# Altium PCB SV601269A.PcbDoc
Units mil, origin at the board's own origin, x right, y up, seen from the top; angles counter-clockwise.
Board outline 2000 x 3100 mil, 4 copper layers (Top Layer, GND_PLANE, POWER_PLANE, Bottom Layer), stack 60.8 mil thick; 63 components, 34 nets, 195 pads, 55 vias.
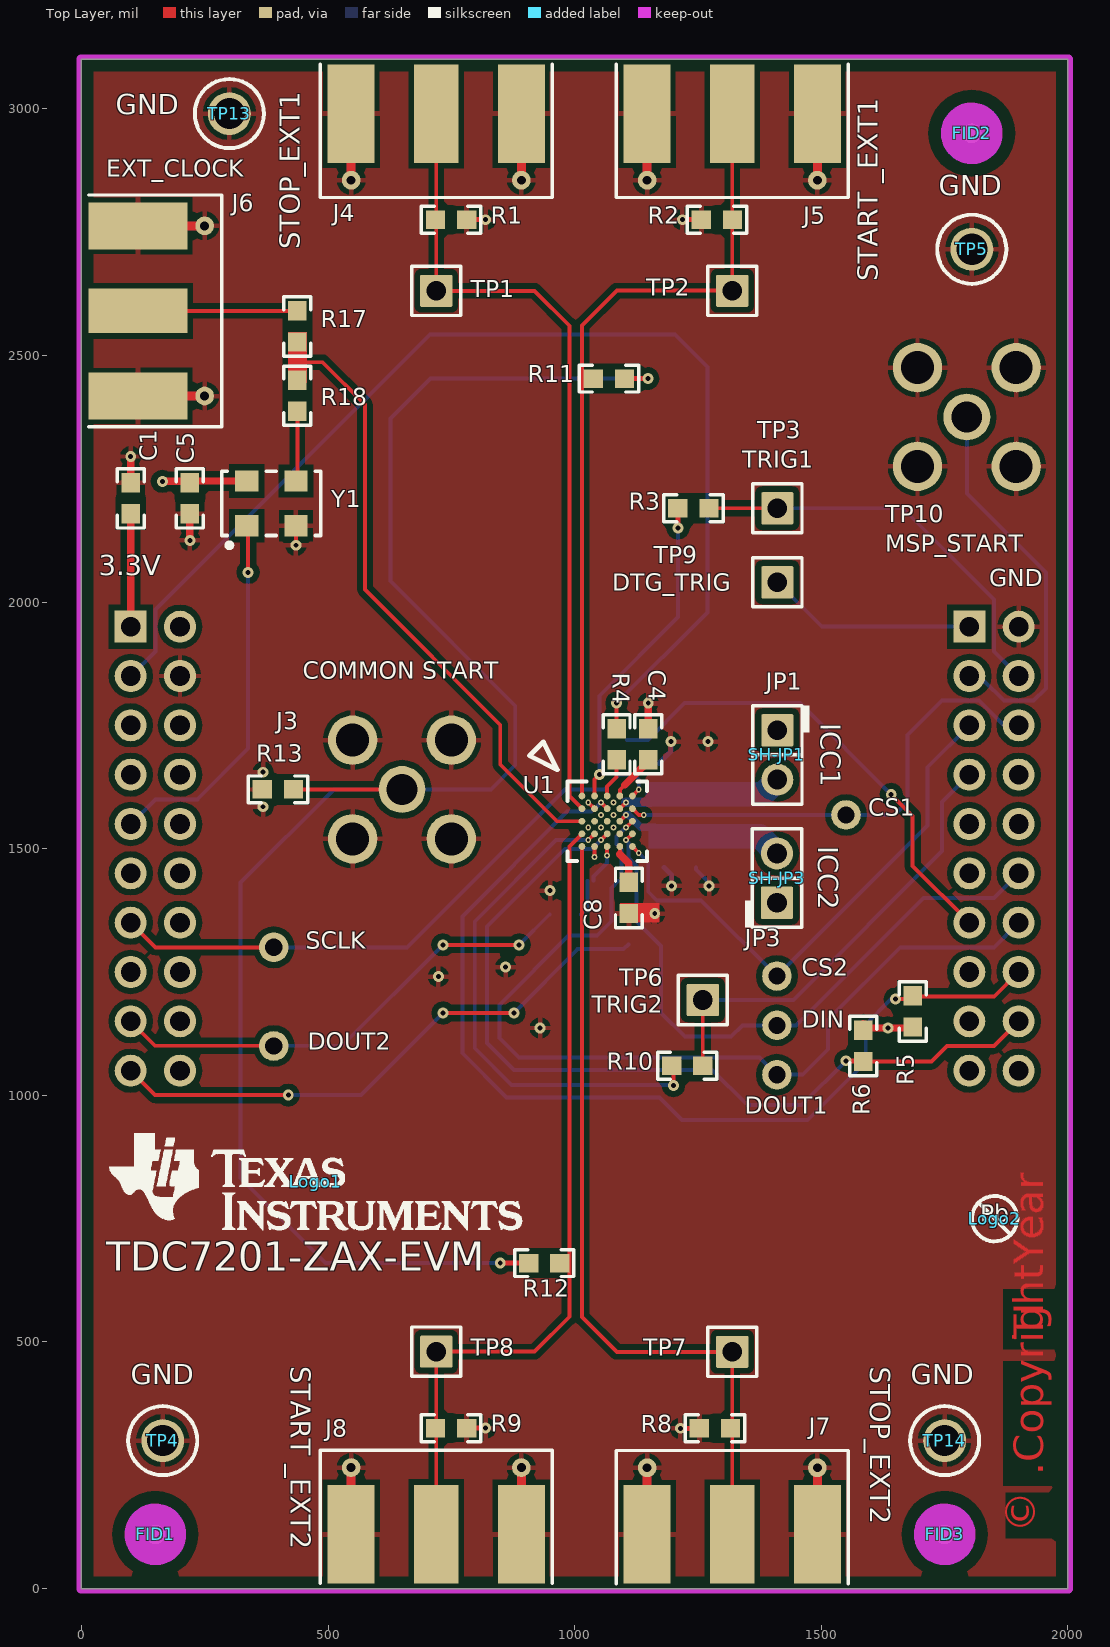
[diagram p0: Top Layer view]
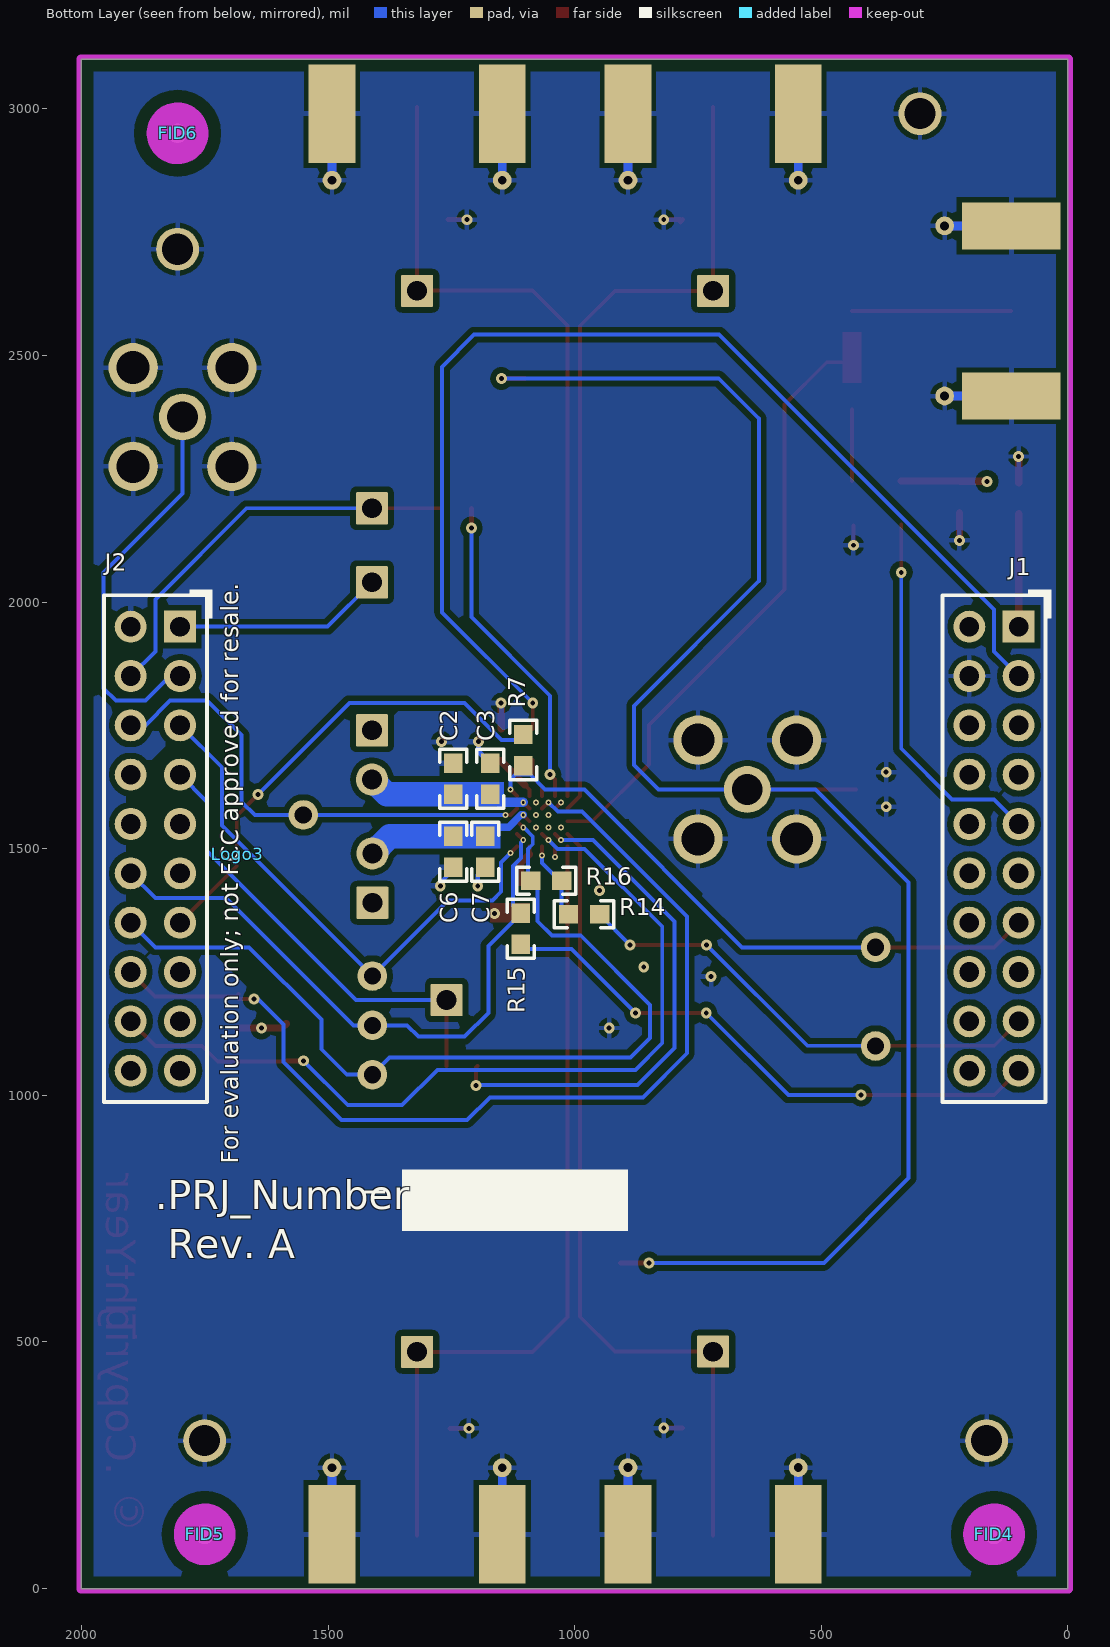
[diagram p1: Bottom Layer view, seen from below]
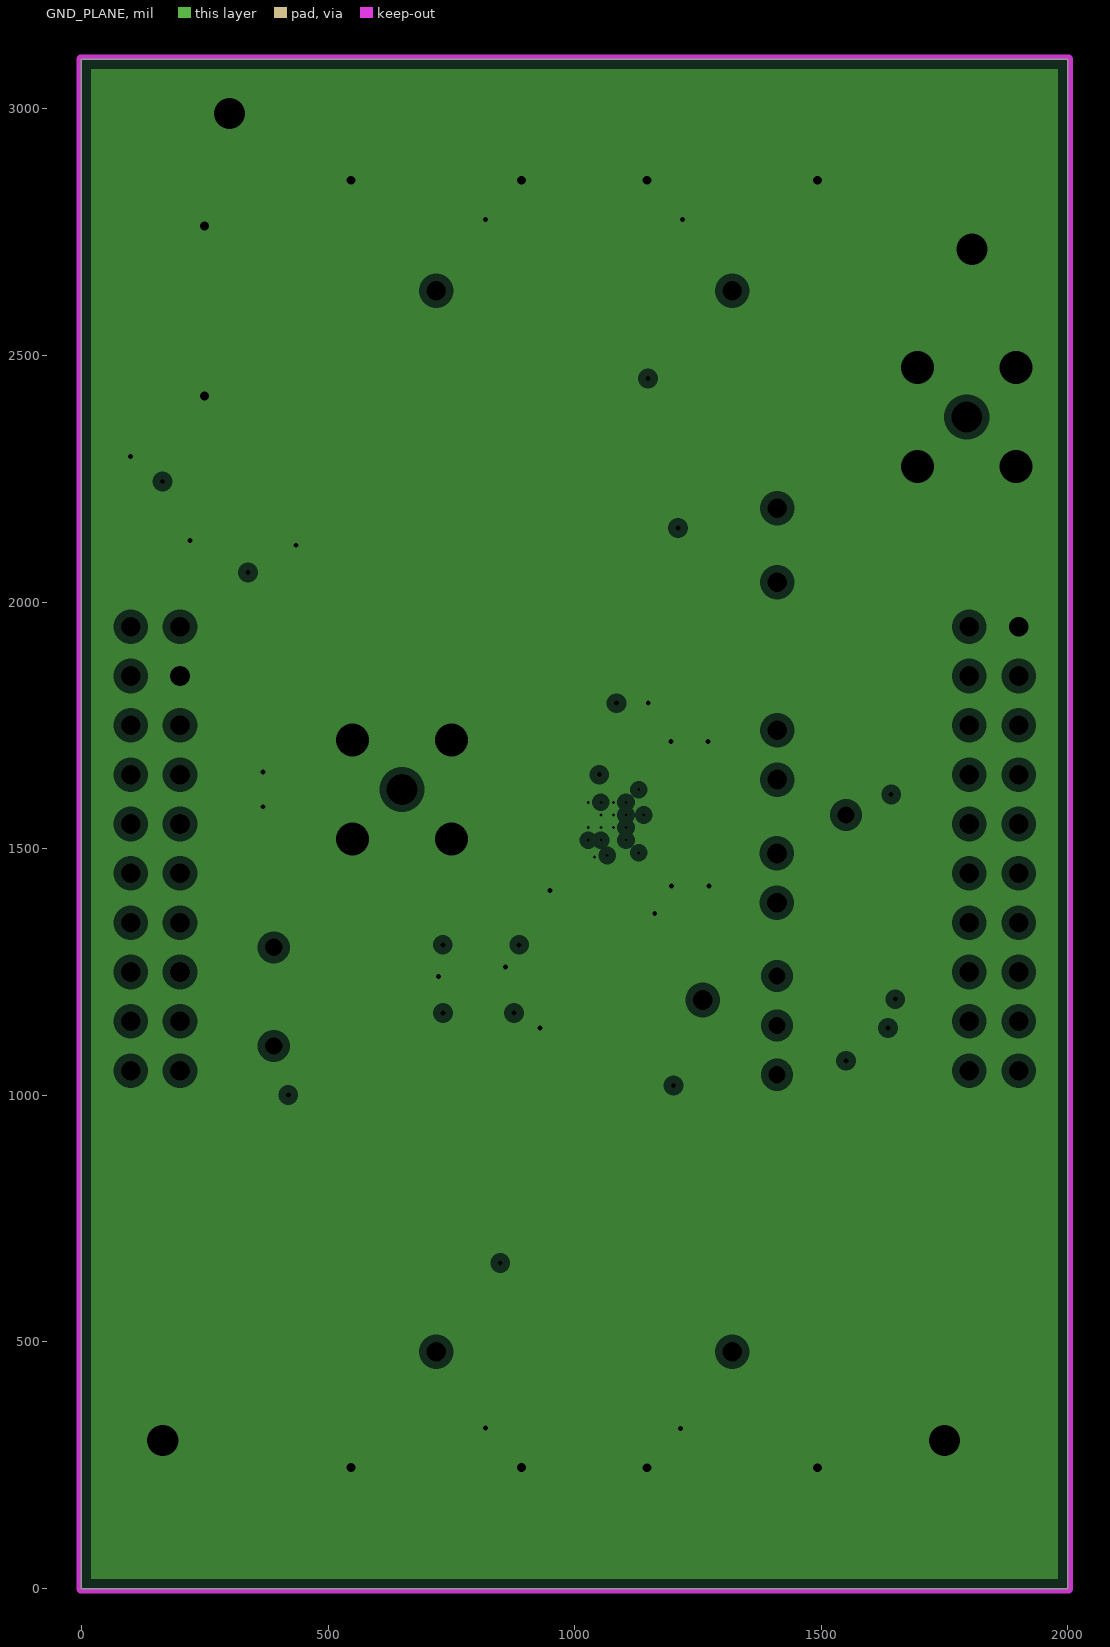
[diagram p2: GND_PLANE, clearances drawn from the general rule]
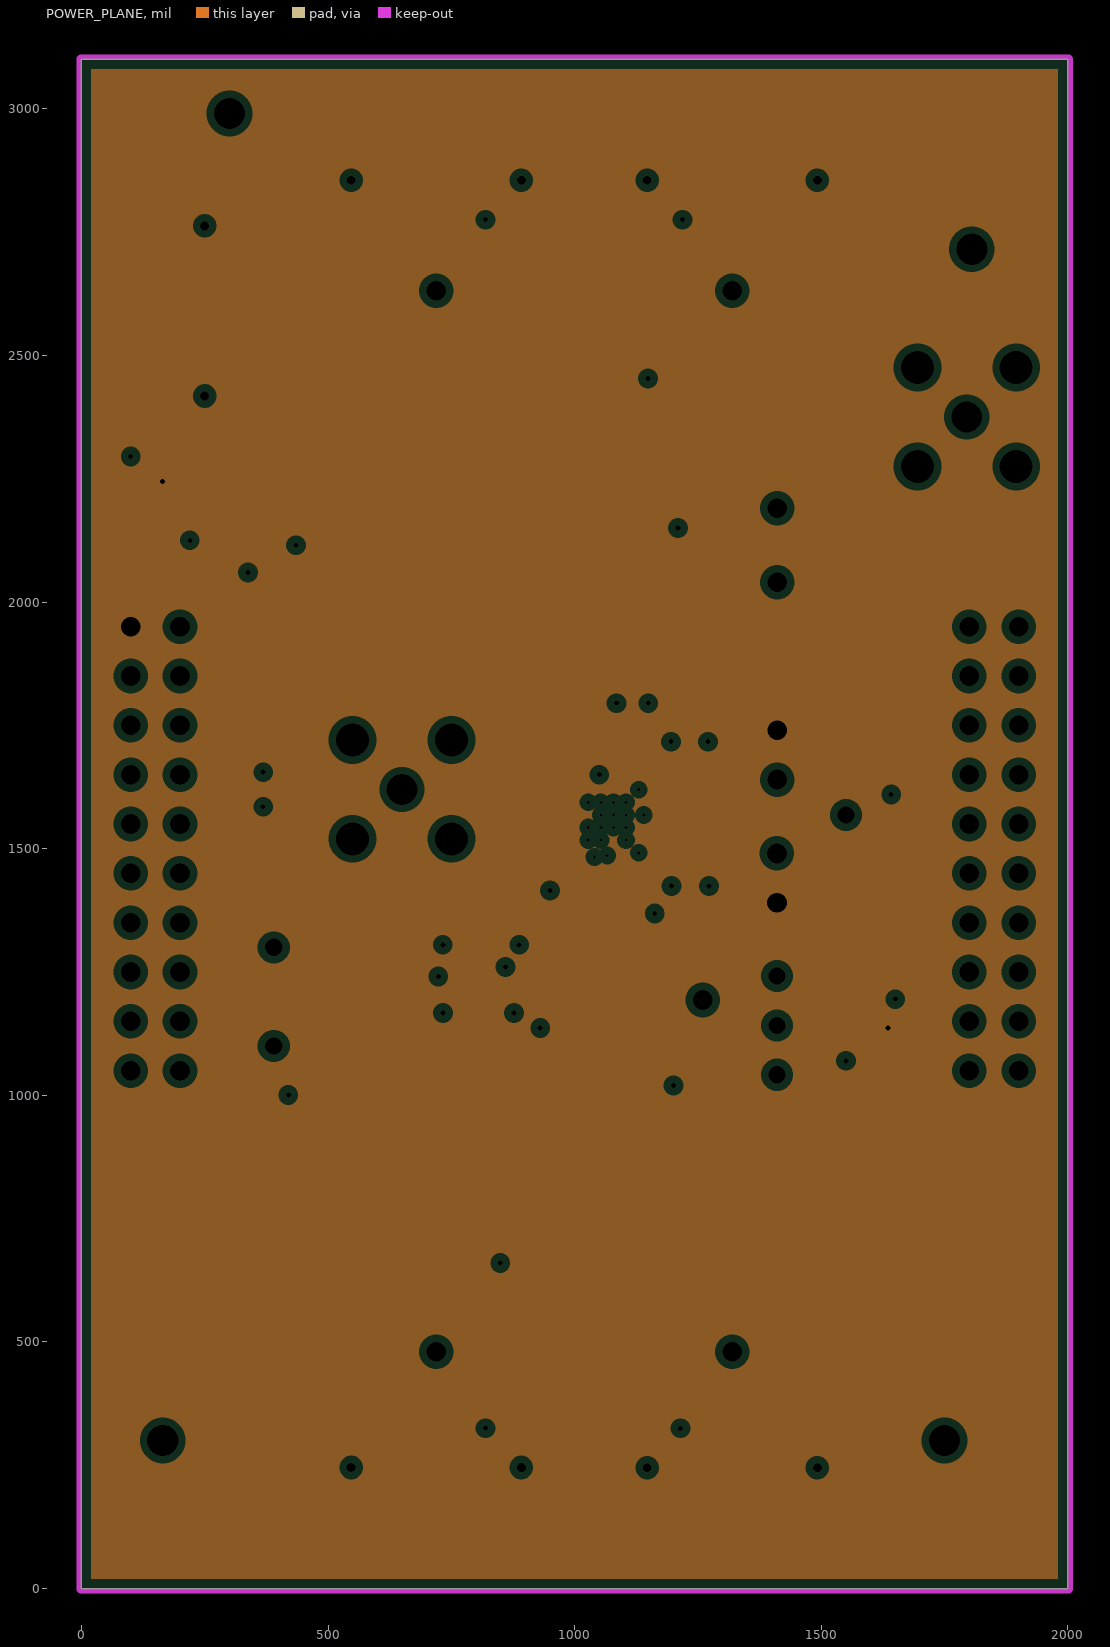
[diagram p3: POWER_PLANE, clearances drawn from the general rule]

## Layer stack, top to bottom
Top Solder: solder mask 0.4, Solder Resist, Dk 3.5
Top Layer: signal copper 1.4
Dielectric1: core 12.6, FR-4 High TG, Dk 4.8
GND_PLANE: plane copper 1.4, net GND
Dielectric2: prepreg 30, FR-4 High TG, Dk 4.8
POWER_PLANE: plane copper 1.4, net VCC
Dielectric3: core 12.6, FR-4 High TG, Dk 4.8
Bottom Layer: signal copper 1.4
Bottom Solder: solder mask 0.4, Solder Resist, Dk 3.5

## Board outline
0,0 0,3100 2000,3100 2000,0

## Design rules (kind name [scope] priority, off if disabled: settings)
AcuteAngle [All] p1: minimum=4.50000000000000E+0001 checktracksonly=FALSE
AssemblyTestPointUsage [All] p1: valid=2
Clearance Clearance_BoardEdge_MountingHoles [OnCopper and InComponentClass('Mounting Holes') vs IsKeepOut] p1: gap=40
Clearance Clearance_BoardEdge_Poly [OnCopper and InPoly vs IsKeepOut] p2: gap=25
Clearance Clearance_BoardEdge [OnCopper and Not InComponentClass('Logo') and not InComponentClass('FiducialMark') and not InRegion(1000,500,4000,800) and Not IsKeepout vs IsKeepOut] p3: gap=5
Clearance Clearance_Poly [InPolygon] p4: gap=12
Clearance [All] p5: gap=6 except(5: Track-THPad SMDPad-Via THPad-Via)
ComponentClearance ComponentClearance_shunt [InComponentClass('Header') vs InComponentClass('Shunt')] p1: gap=0 collisioncheckmode=3 verticalgap=0 showdistances=FALSE
ComponentClearance ComponentClearance_Logo [InComponentClass('Logo')] p2: gap=0 collisioncheckmode=3 verticalgap=0 showdistances=FALSE
ComponentClearance ComponentClearance_ScrewToNut [(HasFootprint('NY PMS 440 0025 PH')) vs (HasFootprint('Keystone_1902C'))] p3: gap=5 collisioncheckmode=3 verticalgap=10 showdistances=FALSE
ComponentClearance ComponentClearance_MountingHoles [InComponentClass('Mounting Holes')] p4: gap=250 collisioncheckmode=3 verticalgap=100000 showdistances=FALSE
ComponentClearance ComponentClearance_SmallPassives [HasFootprint('0201*') or HasFootprint('0402*') or HasFootprint('0508') or HasFootprint('0603*') or HasFootprint('0612') or HasFootprint('0805*') or HasFootprint('0815*') or HasFootprint('0830*') or HasFootprint('1206*') or HasFootprint('1210*') or HasFootprint('1808*') or HasFootprint('1812*') or HasFootprint('1825*') or HasFootprint('2010*') or HasFootprint('2220*') or HasFootprint('2225*') or HasFootprint('2512*') or HasFootprint('2728*') or HasFootprint('3518*') vs HasFootprint('0201*') or HasFootprint('0402*') or HasFootprint('0508') or HasFootprint('0603*') or HasFootprint('0612') or HasFootprint('0805*') or HasFootprint('0815*') or HasFootprint('0830*') or HasFootprint('1206*') or HasFootprint('1210*') or HasFootprint('1808*') or HasFootprint('1812*') or HasFootprint('1825*') or HasFootprint('2010*') or HasFootprint('2220*') or HasFootprint('2225*') or HasFootprint('2512*') or HasFootprint('2728*') or HasFootprint('3518*')] p5: gap=20 collisioncheckmode=3 verticalgap=10 showdistances=FALSE
ComponentClearance ComponentClearance_THtoSMT [IsThruComponent vs IsSMTComponent] p6: gap=20 collisioncheckmode=3 verticalgap=30 showdistances=FALSE
ComponentClearance ComponentClearance_THtoTH [IsThruComponent vs IsThruComponent] p7: gap=20 collisioncheckmode=3 verticalgap=30 showdistances=FALSE
ComponentClearance [All] p8: gap=40 collisioncheckmode=3 verticalgap=10 showdistances=FALSE
DiffPairsRouting [All] p1: maxlimit=100 minlimit=10 mostfreqgap=10 toplayer_minwidth=15 toplayer_maxwidth=15 toplayer_prefwidth=15 bottomlayer_minwidth=15 bottomlayer_maxwidth=15 bottomlayer_prefwidth=15 maxuncoupledlength=1000
FabricationTestPointUsage TestPointUsage [All] p1: valid=2 allowmultiple=FALSE
FabricationTestpoint Testpoint [All] p1: side=3 testpointundercomponent=TRUE minsize=40 maxsize=100 preferedsize=60 minholesize=0 maxholesize=40 preferedholesize=32 testpointgrid=1 allowsidetop=TRUE allowsidebottom=TRUE usegrid=TRUE gridtolerance=0.01
FanoutControl Fanout_LCC [IsLCC] p1: bgadir=Out bgaviamode=Centered fanoutstyle=Auto fanoutdirection=Alternating viagrid=1 // Fanout_LCC (Default Rule)
FanoutControl Fanout_BGA [IsBGA] p2: bgadir=Out bgaviamode=Centered fanoutstyle=Auto fanoutdirection=Alternating viagrid=1 // Fanout_BGA (Default Rule)
FanoutControl Fanout_Default [All] p4: bgadir=Out bgaviamode=Centered fanoutstyle=Auto fanoutdirection=Alternating viagrid=1 // Fanout_Default (Default Rule)
FanoutControl Fanout_Small [(CompPinCount < 5)] p5: bgadir=Out bgaviamode=Centered fanoutstyle=Auto fanoutdirection=OutThenIn viagrid=1 // Fanout_Small (Default Rule)
HoleSize [All] p1: absolutevalues=TRUE maxlimit=251 minlimit=6 maxpercent=80.000 minpercent=20.000
MinimumAnnularRing [All] p1: minimumring=3
MinimumSolderMaskSliver MinimumSolderMaskSliver_Logo [InComponentClass('Logo') vs InComponentClass('Logo')] p1: minsoldermaskwidth=0.7
MinimumSolderMaskSliver [All] p2: minsoldermaskwidth=4
PlaneClearance [All] p1: clearance=15
PlaneConnect PlaneConnect_Thermal_Vias [IsVia] p1: planeconnectstyle=Direct reliefexpansion=20 reliefentries=4 reliefconductorwidth=10 reliefairgap=10
PlaneConnect [All] p2: planeconnectstyle=Relief reliefexpansion=10 reliefentries=4 reliefconductorwidth=10 reliefairgap=10
PolygonConnect [All] p1: connectstyle=Relief reliefconductorwidth=10 reliefentries=4 polygonreliefangle="90 Angle" airgapwidth=10
RoutingVias [All] p1: holewidth=16 width=34 viastyle="Through Hole" minholewidth=6 minwidth=12 maxholewidth=40 maxwidth=65
SMDToCorner [All] p1: distance=16000
SilkToSilkClearance SilkToSilkClearance_Pb_FREE_LOGO [(HasFootprint('Pb-Free_Overlay_Medium') OR HasFootprint('Pb-Free_Overlay_Small')) vs (HasFootprint('Pb-Free_Overlay_Medium') OR HasFootprint('Pb-Free_Overlay_Small'))] p1: silktosilkclearance=0
SilkToSilkClearance [All] p2: silktosilkclearance=4
SilkToSolderMaskClearance SilkscreenOverComponentPads [IsPad] p1: minsilkscreentomaskgap=4 clearancetoexposedcopper=TRUE
SolderMaskExpansion [All] p1: expansion=1
Width [All] p1: maxlimit=100 minlimit=7.8 preferedwidth=10
15 further rules are at their usual default settings.

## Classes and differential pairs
component class AssemblyNote: ZZ1 ZZ2
component class Header: JP1 JP3 TP1 TP2 TP3 TP6 TP7 TP8 TP9
component class Shunt: SH-JP1 SH-JP3
component class Logo: Logo1
component class FiducialMark: FID1 FID2 FID3 FID4 FID5 FID6

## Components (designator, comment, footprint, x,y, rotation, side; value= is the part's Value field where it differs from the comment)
C1 "C0603C106M9PACTU" 0603 100,2210 r90 top
C2 "0603YC104JAT2A" 0603 1245.97,1641.5 r90 bottom
C3 "06031C103JAT2A" 0603 1170.97,1641.5 r90 bottom
C4 "EMK107B7105KA-T" 0603 1149.12,1711.5 r270 top
C5 "06031C103JAT2A" 0603 220,2210 r270 top
C6 "0603YC104JAT2A" 0603 1245.97,1493.5 r270 bottom
C7 "06031C103JAT2A" 0603 1180.97,1493.5 r270 bottom
C8 "EMK107B7105KA-T" 0603 1110,1400 r90 top
FID1 "Fiducial" Fiducial10-30 150,110 r0 top
FID2 "Fiducial" Fiducial10-30 1805,2950 r0 top
FID3 "Fiducial" Fiducial10-30 1750,110 r0 top
FID4 "Fiducial" Fiducial10-30 150,110 r180 bottom
FID5 "Fiducial" Fiducial10-30 1750,110 r180 bottom
FID6 "Fiducial" Fiducial10-30 1805,2950 r180 bottom
J1 "PPPC102LFBN-RC" Sullins_PPPC102LFBN-RC 150,1500 r90 bottom
J2 "PPPC102LFBN-RC" Sullins_PPPC102LFBN-RC 1850,1500 r90 bottom
J3 "142-0701-201" Johnson_142-0701-20x 650,1620 r180 top
J4 "142-0701-801" JOHNSON_142-0701-801 719.41,2990 r0 top
J5 "142-0701-801" JOHNSON_142-0701-801 1319.41,2990 r0 top
J6 "142-0701-801" JOHNSON_142-0701-801 115,2590 r90 top
J7 "142-0701-801" JOHNSON_142-0701-801 1319.41,110.03 r180 top
J8 "142-0701-801" JOHNSON_142-0701-801 719.41,110.41 r180 top
JP1 "TSW-102-07-G-S" TSW-102-07-G-S 1410.83,1690 r270 top
JP3 "TSW-102-07-G-S" TSW-102-07-G-S 1410,1440.35 r90 top
Logo1 "Texas Instruments" TI_Stacked_Overlay_Small 475,825 r0 top
Logo2 "Pb-Free Symbol" Pb-Free_Overlay_Small 1851.28,750 r0 top
Logo3 "FCC disclaimer" FCC_disclaimer 1683.24,1488.87 r90 bottom
R1 "CRCW060349R9FKEA" 0603 749.41,2775 r180 top
R2 "CRCW060349R9FKEA" 0603 1288.41,2775 r0 top
R3 "CRCW06030000Z0EA" 0603 1240.83,2190 r0 top
R4 "CRCW06030000Z0EA" 0603 1085,1711.5 r90 top
R5 "CRCW060310K0FKEA" 0603 1685,1170 r270 top
R6 "CRCW060310K0FKEA" 0603 1585,1100 r90 top
R7 "CRCW06030000Z0EA" 0603 1104.27,1700 r90 bottom
R8 "CRCW060349R9FKEA" 0603 1284.41,325.03 r0 top
R9 "CRCW060349R9FKEA" 0603 749.41,325.41 r180 top
R10 "CRCW06030000Z0EA" 0603 1228.15,1059.72 r0 top
R11 "CRCW06030000Z0EA" 0603 1069.5,2453 r180 top
R12 "CRCW06030000Z0EA" 0603 938.5,660 r0 top
R13 "CRCW060349R9FKEA" 0603 398.5,1620 r0 top
R14 "CRCW06030000Z0EA" 0603 981,1367 r0 bottom
R15 "CRCW06030000Z0EA" 0603 1109,1337.45 r90 bottom
R16 "CRCW06030000Z0EA" 0603 1057.8,1435 r180 bottom
R17 "CRCW06030000Z0EA" 0603 438,2558.5 r90 top
R18 "CRCW06030000Z0EA" 0603 438,2418 r90 top
SH-JP1 "969102-0000-DA" SNT-100-BK-G 1410,1690 r90 top
SH-JP3 "969102-0000-DA" SNT-100-BK-G 1411,1439.64 r90 top
TP1 "TSW-101-07-G-S" TSW-101-07-G-S 719.41,2630.77 r0 top
TP2 "TSW-101-07-G-S" TSW-101-07-G-S 1319.41,2630.77 r0 top
TP3 "TSW-101-07-G-S" TSW-101-07-G-S 1410.83,2190 r0 top
TP4 "5011" Keystone5011 165,300 r0 top
TP5 "5011" Keystone5011 1805,2715 r0 top
TP6 "TSW-101-07-G-S" TSW-101-07-G-S 1259.65,1193.22 r180 top
TP7 "TSW-101-07-G-S" TSW-101-07-G-S 1319.41,480.03 r180 top
TP8 "TSW-101-07-G-S" TSW-101-07-G-S 719.41,480.41 r180 top
TP9 "TSW-101-07-G-S" TSW-101-07-G-S 1410.83,2040 r0 top
TP10 "142-0701-201" Johnson_142-0701-20x 1795,2375 r90 top
TP13 "5011" Keystone5011 300,2990 r0 top
TP14 "5011" Keystone5011 1750,300 r0 top
U1 "TDC7201ZAXR" ZAX0025A 1065.88,1555.59 r0 top locked
Y1 "ASFLMB-8.000MHZ-LY-T" Abracon_ASFLMB 385,2200 r90 top
ZZ1 "Short SH-JP1 on JP1 pin 1-2" AssemblyNote 175,3820 r0 top
ZZ2 "Short SH-JP3 on JP3 pin 1-2" AssemblyNote 175,3700 r0 top

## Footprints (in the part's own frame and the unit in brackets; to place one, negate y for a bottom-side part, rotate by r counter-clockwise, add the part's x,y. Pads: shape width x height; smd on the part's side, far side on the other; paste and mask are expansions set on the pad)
0603 [mm] "0603 from SM-752 data"
  rect 1x0.95 smd: 1(-0.8,0) 2(0.8,0)
  silkscreen extent -1.52,-0.69 1.52,0.69, body extent -0.87,-0.47 0.87,0.47, height 1
Abracon_ASFLMB [mm] "Abracon"
  rect 1.1x1.2 smd: 1(-1.15,1.27) 2(-1.15,-1.27) 3(1.15,-1.27) 4(1.15,1.27)
  silkscreen extent -2.29,-2.55 1.65,2.55, body extent -1.65,-2.55 1.65,2.55, height 0.9
AssemblyNote [mil] "Assembly Note"
FCC_disclaimer [mil]
Fiducial10-30 [mm]
  round 1 smd mask+1: 1(0,0)
  Top Layer keep-out circle w1.678: c0,0 r0.75
Johnson_142-0701-20x [mil] "Johnson Components recommended land pattern"
  round 95 hole 62: 1(0,0)
  round 100 hole 67: 2(100,100) 3(100,-100) 4(-100,-100) 5(-100,100)
  body extent -156,-156 156,156, height 375
JOHNSON_142-0701-801 [mil] "Johnson Components recommended land pattern"
  rect 90x200 smd: 1(0,0)
  round 38 hole 18: 2(-172.5,-135) 3(172.5,-135)
  rect 95x200 smd: 2(-172.5,0) 3(172.5,0)
  rect 95x200 smd far side: 4(-172.5,0) 5(172.5,0)
  Top Layer lines w18: -172.5,-135 -172.5,0 ; 172.5,-135 172.5,0
  Bottom Layer lines w18: -172.5,-135 -172.5,0 ; 172.5,-135 172.5,0
  silkscreen extent -235,-170 235,100, body extent -190,-92 190,480, height 165
Keystone5011 [mil] "Keystone Multipurpose loops"
  round 87 hole 63: 1(0,0)
  silkscreen extent -70,-70 70,70, body extent -63,-63 63,62, height 319
Pb-Free_Overlay_Small [mil]
  silkscreen extent -46,-46 46,46
SNT-100-BK-G [mil] "Samtec STEP model"
  round 1 on Mech3: 0(0,0)
  body extent -100,-50 100,50, height 344
Sullins_PPPC102LFBN-RC [mil] "Sullins"
  rect 65x65 hole 40: 1(450,-50)
  round 65 hole 40: 2(450,50) 3(350,-50) 4(350,50) 5(250,-50) 6(250,50) 7(150,-50) 8(150,50) 9(50,-50) 10(50,50) 11(-50,-50) 12(-50,50) 13(-150,-50) 14(-150,50) 15(-250,-50) 16(-250,50) 17(-350,-50) 18(-350,50) 19(-450,-50) 20(-450,50)
  silkscreen extent -514,-116 526,104, body extent -514,-104 514,104, height 335
TI_Stacked_Overlay_Small [mil]
  silkscreen extent -418,-98 418,98
TSW-101-07-G-S [mm] "Samtec 100mil, 1pos, 230 mil above insulator"
  rrect6% 1.65x1.65 hole 1.016: 1(0,0)
  silkscreen extent -1.27,-1.27 1.27,1.27, body extent -1.27,-1.27 1.27,1.27, height 8.38
TSW-102-07-G-S [mm] "Samtec 100mil, 1x2, 230 mil above insulator"
  rrect6% 1.65x1.65 hole 1.016: 1(-1.27,0)
  round 1.65 hole 1.016: 2(1.27,0)
  silkscreen extent -2.54,-1.27 2.54,1.65, body extent -2.54,-1.27 2.54,1.27, height 8.38
ZAX0025A [mm] "BGA, 25-Leads, Body 4x4mm, Pitch 0.65mm"
  round 0.35 smd mask+0: A1(-1.3,1.3) A2(-0.65,1.3) A3(0,1.3) A4(0.65,1.3) A5(1.3,1.3) B1(-1.3,0.65) B2(-0.65,0.65) B3(0,0.65) B4(0.65,0.65) B5(1.3,0.65) C1(-1.3,0) C2(-0.65,0) C3(0,0) C4(0.65,0) C5(1.3,0) D1(-1.3,-0.65) D2(-0.65,-0.65) D3(0,-0.65) D4(0.65,-0.65) D5(1.3,-0.65) E1(-1.3,-1.3) E2(-0.65,-1.3) E3(0,-1.3) E4(0.65,-1.3) E5(1.3,-1.3)
  silkscreen extent -2.05,-2.05 2.05,2.05, body extent -2.05,-2.05 2.05,2.05, height 1.2

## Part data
C1: "CAP, CERM, 10 µF, 6.3 V, +/- 20%, X5R, 0603"
C2 C6: "CAP, CERM, 0.1 µF, 16 V, +/- 5%, X7R, 0603"
C3 C5 C7: "CAP, CERM, 0.01 µF, 100 V, +/- 5%, X7R, 0603"
C4 C8: "CAP, CERM, 1 µF, 16 V, +/- 10%, X7R, 0603"
FID1 FID2 FID3 FID4 FID5 FID6: "Fiducial mark.  There is nothing to buy or mount."
J1 J2: "Receptacle, 100mil, 10x2, Gold, TH"
J3 TP10: "Connector, TH, SMA"
J4 J5 J6 J7 J8: "Connector, End launch SMA, 50 ohm, SMT"
JP1 JP3: "Header, 100mil, 2x1, Gold, TH"
Logo1: library part TI_Logo, "Texas Instrument Corporate Signature"
Logo2: library part Pb-Free
Logo3: library part FCC_disclaimer, "FCC_disclaimer"
R1 R2 R8 R9 R13: "RES, 49.9, 1%, 0.1 W, 0603"
R3 R4 R7 R10 R11 R12 R14 R15 R16 R17 R18: "RES, 0, 5%, 0.1 W, 0603"
R5 R6: "RES, 10.0 k, 1%, 0.1 W, 0603"
SH-JP1 SH-JP3: "Shunt, 100mil, Gold plated, Black"
TP1 TP2 TP3 TP6 TP7 TP8 TP9: "Header, 100mil, 1pos, Gold, TH"
TP4 TP5 TP13 TP14: "Test Point, Multipurpose, Black, TH"
U1: "Time-to-Digital Converter for Time-of-FlightApplications in LIDAR, Magnetostrictive andFlowMeters, ZAX0025A"
Y1: "OSC, 8MHz, 15pF, SMD"
ZZ1 ZZ2: library part AssemblyNote

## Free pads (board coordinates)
  round 60 hole 35: 0(390,1100) 0(390,1300) 0(1410,1041.77) 0(1410,1141.77) 0(1410,1241.77) 0(1550,1568.39)

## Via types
v1: diameter 22, hole 10, Top Layer to Bottom Layer, tented both sides, 36 vias
v2: diameter 12, hole 6, Top Layer to Bottom Layer, tented both sides, 19 vias

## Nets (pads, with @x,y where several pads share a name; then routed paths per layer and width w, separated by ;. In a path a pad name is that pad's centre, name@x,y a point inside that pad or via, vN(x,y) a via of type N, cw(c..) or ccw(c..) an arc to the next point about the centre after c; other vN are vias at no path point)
CLOCK_TDC_CAL: R17.1 R18.2 U1.C1 | length 1222.6
  Top Layer w8: 444,2486 489,2486 575,2400 575,2025 849.09,1750.91 849.09,1670.91 964.41,1555.59 U1.C1
CS1: J2.6 pad.0@1550,1568.39 U1.B5 | length 979
  Top Layer w8: U1.B5 1129.86,1568.39 v2(1140,1568.39)
  Bottom Layer w8: v2@1145,1568.39 1648.39,1568.39 1675,1595 1675,1730 1745,1800 1820,1800 1870,1750 J2.6
CS2: J2.5 pad.0@1410,1241.77 U1.E5 | length 1106.5
  Top Layer w8: U1.E5 v2(1129.86,1491.61)
  Bottom Layer w8: v2(1129.86,1491.61) 1149.12,1472.35 1149.12,1412.66 1166.44,1395.34 1256.44,1395.34 1410,1241.77 1715,1546.77 1715,1665 J2.5
DIN: J2.12 pad.0@1410,1141.77 R15.2 U1.D5 | length 1292.8
  Top Layer w8: v2(1104.27,1517.2) U1.D5
  Bottom Layer w8: v2(1104.27,1517.2) 1109,1512.47 1109,1481 1125,1465 1125,1384.94 R15.2 1175,1302.94 1175,1167.21 1223.31,1118.9 1317,1118.9 1339.87,1141.77 1410,1141.77 1448.57,1141.77 1706.8,1400 1850,1400 J2.12
DOUT1: J2.14 pad.0@1410,1041.77 R16.1 U1.C5 | length 1827.9
  Top Layer w8: v2(1104.27,1542.8) U1.C5
  Bottom Layer w8: R16.1 1075,1420.7 1075,1352.91 1045.8,1323.72 987.72,1323.72 847.5,1183.5 847.5,1116.42 887.23,1076.69 1375.08,1076.69 1410,1041.77 1461.77,1041.77 1513.39,1093.39 1513.39,1153.39 1660,1300 1850,1300 J2.14 ; R16.1@1095,1445 1095,1499 1085,1509 1085,1525 1102.8,1542.8 v2(1104.27,1542.8)
DOUT2: R14.2 R16.2 U1.E3 | length 154.5
  Top Layer w8: v2(1065.88,1486.31) U1.E3
  Bottom Layer w8: R14.2 1026.3,1380.81 R16.2 ; R16.2@1038.5,1435 1038.5,1443.5 1065.88,1470.88 v2(1065.88,1486.31)
DTG_TRIG: J2.1 TP9.1 | length 426.4
  Bottom Layer w8: TP9.1 1500.83,1950 J2.1
ENABLE1: J1.3 R4.2 | length 2342.4
  Top Layer w8: R4.2 v1(1085,1795)
  Bottom Layer w8: J1.3 150,1900 150,1985 707,2542 1203.65,2542 1269,2476.65 1269,1979 v1(1085,1795)
EXT_CLOCK: J6.1 R17.2 | length 323
  Top Layer w8: J6.1 R17.2
GND: C1.2 C2.2 C3.2 C4.1 C5.2 C6.2 C7.2 C8.1 J1.4 J2.2 J3.2 J3.3 J3.4 J3.5 J4.2 J4.3 J4.4 J4.5 J5.2 J5.3 J5.4 J5.5 J6.2 J6.3 J6.4 J6.5 J7.2 J7.3 J7.4 J7.5 J8.2 J8.3 J8.4 J8.5 R1.1 R2.1 R8.1 R9.1 R13.1 TP4.1 TP5.1 TP10.2 TP10.3 TP10.4 TP10.5 TP13.1 TP14.1 U1.B2 U1.E2 Y1.2 | length 545.9
  Top Layer w8: v1(435,2115) Y1.2 ; v2(1027.5,1593.98) U1.B2 ; v2(1040.29,1483.31) U1.E2
  Top Layer w10: R9.1 v1(819.41,325.41) ; R1.1 R1.1@785.91,2770 ; R1.1@785.91,2775 v1(819.41,2775) ; v1(1214.41,325.03) R8.1 ; v1(1218.41,2775) R2.1
  Top Layer w15: C1.2 v1(100,2295) ; v1(220,2125) C5.2@220,2181.5 ; C4.1 v1(1149.12,1795)
  Bottom Layer w8: v2(1027.5,1593.98) v2@1027.5,1594.95 ; v2(1040.29,1483.31) v2@1041.82,1483.31 ; C6.2 1245.97,1457.61 1272.36,1431.22 v1(1272.36,1424.5)
  Bottom Layer w10: C3.2 1195.07,1697.09 v1(1195.07,1717) ; C7.2 1196.5,1446.48 v1(1196.5,1424.5)
  other v1: 930,1136.5 723.7,1240.71 860,1260 1162.29,1368.5 950,1415 368.5,1585 368.5,1655 1270.07,1717
  other v2: 1027.5,1542.8 1053.09,1542.8 1078.68,1542.8 1053.09,1568.39 1078.68,1568.39 1078.68,1593.98
INT1: J2.16 R5.1 U1.B3 | length 2023.2
  Top Layer w8: v2(1053.09,1593.98) U1.B3 ; v1(1650,1195) R5.1@1681.5,1195 ; R5.1@1681.5,1205 R5.1 ; R5.1@1686,1200.5 1850.5,1200.5 J2.16
  Bottom Layer w8: v2@1053.09,1594.95 v2(1053.09,1593.98) 1034.11,1575 984.84,1575 772.5,1362.66 772.5,1085.35 861.85,996 1171.95,996 1217.95,950 1472.43,950 1590,1067.57 1590,1143.39 1641.61,1195 v1(1650,1195)
INT2: J2.18 R6.1 U1.D3 | length 1758.5
  Top Layer w8: v2(1053.09,1517.2) U1.D3 ; R6.1 1723.5,1068.5 1755,1100 1850,1100 J2.18
  Top Layer w10: v1(1550,1070) 1583.5,1070 R6.1
  Bottom Layer w8: v2(1053.09,1517.2) 1035.2,1499.31 979.87,1499.31 822.5,1341.95 822.5,1106.06 876.87,1051.69 1278.31,1051.69 1350,980 1460,980 v1(1550,1070)
MSP_START: J2.3 TP10.1 | length 802.3
  Bottom Layer w8: TP10.1 1795,2220 1955,2060 1955,1825 1930,1800 1870,1800 1830,1840 1825,1840 1815,1850 J2.3
NetJ1_17: J1.17 pad.0@390,1100 R14.1 | length 968.7
  Top Layer w8: J1.17 149.5,1100.5 pad.0@385,1100.5 ; v1@733.3,1305 876.3,1305
  Bottom Layer w8: pad.0@385,1100.5 528.3,1100.5 v1(732.8,1305) ; v1(887.5,1305) R14.1
NetJ1_19: J1.19 R15.1 | length 1156
  Top Layer w8: J1.19 149.5,1000.5 v1(419.5,1000.5) ; v1(733.3,1166.8) v1(876.8,1166.8)
  Bottom Layer w8: v1(419.5,1000.5) 566.99,1000.5 v1(733.3,1166.8) ; v1(876.8,1166.8) 1006.18,1296.18 1099.23,1296.18 R15.1
NetJ2_13: J2.13 R7.2 | length 968.7
  Top Layer w8: v1(1641.61,1610) 1685,1566.61 1685,1465 J2.13
  Bottom Layer w8: R7.2@1106,1720.5 1148.5,1720.5 1223,1795 1456.61,1795 v1(1641.61,1610)
NetJ3_1: J3.1 R11.1 R12.1 R13.2 | length 3539.8
  Top Layer w8: R13.2 J3.1
  Top Layer w10: v1(849.09,660) R12.1 ; R11.1 v1(1148.67,2453)
  Bottom Layer w8: v1(849.09,660) 495,660 323,832 323,1431 512,1620 J3.1 830,1620 879.6,1669.6 879.6,1789.4 626.8,2042.2 626.8,2371.8 708,2453 v1(1148.67,2453)
NetR3_1: R3.1 U1.A2 | length 653.2
  Top Layer w8: U1.A2 1040.29,1640.29 v1(1050,1650)
  Top Layer w10: v1(1209.33,2150) R3.1
  Bottom Layer w8: v1(1050,1650) 1050,1810 1209.33,1969.33 v1(1209.33,2150)
NetR4_1: R4.1 U1.A3 | length 81.1
  Top Layer w8: U1.A3 1065.88,1625.88 1085,1645 R4.1
NetR10_1: R10.1 U1.D2 | length 1048.6
  Top Layer w8: v2(1027.5,1517.2) U1.D2 ; R10.1 1200.16,1056.21 v1(1200.16,1019.72)
  Bottom Layer w8: v2(1027.5,1517.2) 962.4,1517.2 797.5,1352.3 797.5,1095.71 872.21,1021 1198.87,1021 v1(1200.16,1019.72)
OSC_ENABLE: J1.9 Y1.1 | length 755.1
  Top Layer w8: v1(338,2060) Y1.1@338,2156.69
  Bottom Layer w8: J1.9 150,1600 235,1600 338,1703 v1(338,2060)
OSC_OUT: R18.1 Y1.3 | length 144.7
  Top Layer w8: Y1.3@438,2245.28 R18.1@438,2390
SCLK: J1.13 pad.0@390,1300 R7.1 U1.A5 | length 1238.2
  Top Layer w8: J1.13 150,1300 pad.0@390,1300 ; U1.A5 v2(1129.86,1619.57)
  Bottom Layer w8: pad.0@390,1300 660.4,1300 980.4,1620 1060,1620 1090,1650 1119.86,1650 1129.86,1640 v2(1129.86,1619.57)
START_EXT1: J5.1 R2.2 R11.2 TP2.1 U1.A1 | length 1660.6
  Top Layer w8: U1.A1 1014.7,2560.38 1085.47,2631.15 TP2.1@1319.41,2631.15 ; TP2.1 J5.1@1319.41,3003.77
START_EXT2: J8.1 R9.2 R12.2 TP8.1 U1.D1 | length 1661.4
  Top Layer w8: J8.1@719.41,107.41 TP8.1 918.31,480.41 989.11,551.21 989.11,1504.41 U1.D1
STOP_EXT1: J4.1 R1.2 TP1.1 U1.B1 | length 1661.4
  Top Layer w8: J4.1@719.41,3003.77 TP1.1 918.31,2630.77 989.11,2559.97 989.11,1606.77 U1.B1
STOP_EXT2: J7.1 R8.2 TP7.1 U1.E1 | length 1660.6
  Top Layer w8: U1.E1 1014.7,550.8 1085.47,480.03 TP7.1 ; J7.1@1319.41,107.41 TP7.1@1319.41,480.41
TRIG1: J2.4 R3.2 TP3.1 | length 817
  Top Layer w8: R3.2 TP3.1@1397.83,2190
  Bottom Layer w8: TP3.1 1665,2190 1850,2005 1850,1900 J2.4
TRIG2: J2.7 R10.2 TP6.1 | length 921.6
  Top Layer w8: R10.2 TP6.1
  Bottom Layer w8: TP6.1 1443.22,1193.22 1745,1495 1745,1595 J2.7
VCC: C1.1 C5.1 J1.1 JP1.1 JP3.1 R5.2 R6.2 Y1.4 | length 504.7
  Top Layer w15: J1.1 C1.1 ; v1(164.5,2244.5) C5.1@220,2244.5 ; C5.1@220.78,2245.28 Y1.4@338,2245.28 ; R6.2@1585,1145 1593.5,1136.5 R5.2@1684.99,1136.5
  other v1: 1635,1136.5
VDD1: C2.1 C3.1 JP1.2 U1.B4 | length 343.7
  Top Layer w8: U1.B4 v2(1104.27,1593.98)
  Bottom Layer w20: v2(1104.27,1593.98) 1154.95,1593.98 C3.1
  Bottom Layer w50: C3.1 C2.1 1380.83,1610 JP1.2
VDD2: C6.1 C7.1 JP3.2 U1.C4 | length 356
  Top Layer w8: U1.C4 v2(1104.27,1568.39)
  Bottom Layer w15: v2(1104.27,1568.39) 1108.68,1568.39 1133.96,1543.11 1162.87,1543.11 C7.1
  Bottom Layer w50: C7.1 C6.1 1375,1525 JP3.2@1409.82,1490.18
VREG1: C4.2 U1.A4 | length 97.1
  Top Layer w8: U1.A4 1091.47,1619.41 1101.18,1629.12
  Top Layer w12: C4.2@1149.12,1677.05 C4.2
  Top Layer w15: 1101.18,1629.12 C4.2@1149.12,1677.05
VREG2: C8.2 U1.E4 | length 88.7
  Top Layer w8: 1091.47,1489.03 U1.E4
  Top Layer w10: C8.2@1104.27,1437.23 C8.2
  Top Layer w15: 1091.47,1489.03 1110,1470.5 C8.2
pads on no net: FID1.1 FID2.1 FID3.1 FID4.1 FID5.1 FID6.1 J1.2 J1.5 J1.6 J1.7 J1.8 J1.10 J1.11 J1.12 J1.14 J1.15 J1.16 J1.18 J1.20 J2.8 J2.9 J2.10 J2.11 J2.15 J2.17 J2.19 J2.20 SH-JP1.0 SH-JP3.0 U1.C2 U1.C3 U1.D4

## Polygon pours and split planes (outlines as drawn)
GND on Top Layer "Top Layer-GND" (solid, remove dead copper, pour order 2): 0,3100 0,0 2000,0 2000,3100
GND on Bottom Layer "Bottom Layer-GND" (solid, pour order 4): 0,3100 0,0 2000,0 2000,3100
GND on GND_PLANE (split plane): 1979.9,20.1 20.1,20.1 20.1,3079.9 1979.9,3079.9
VCC on POWER_PLANE (split plane): 1979.9,20.1 20.1,20.1 20.1,3079.9 1979.9,3079.9

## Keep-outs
Keep-Out Layer:
  lines w10: -5,0 ccw(c0,0) 0,-5 ; -5,0 ccw(c0,0) 0,-5 ; -5,0 -5,3100 ; -5,3100 cw(c0,3100) 0,3105 ; -5,3100 cw(c0,3100) 0,3105 ; 0,-5 2000,-5 ; 0,3105 2000,3105 ; 2000,-5 ccw(c2000,0) 2005,0 ; 2000,-5 ccw(c2000,0) 2005,0 ; 2000,3105 cw(c2000,3100) 2005,3100 ; 2000,3105 cw(c2000,3100) 2005,3100 ; 2005,0 2005,3100
  text ".Layer_Name" at 577,-858.49 h60

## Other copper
Top Layer:
  rectangle net GND: 1091.47,1350 1171.79,1390.35
  rectangle net CLOCK_TDC_CAL: 419,2444 457,2547
  text "TI" at 1950,506 h60 r90
  text ".CopyrightYear" at 1950,230 h60 r90
  text "©" at 1953.52,113 h105 r90
  text ".Layer_Name" at 577,-858.49 h60
Bottom Layer:
  rectangle net VDD1: 1143.43,1585 1180.97,1635
  rectangle net VDD2: 1150,1500 1190.97,1550
  pour cut-out: 889,1557.63 801.68,1470.32 740.68,1409.32 824.75,1339.7 879,1458.63 988,1458.63 992.37,1463 1145,1463 1145,1557.07 1141.86,1560.21 889,1560.21
  pour cut-out: 1159,1072.44 1407,1072.44 1404,1069.44 1404,956 1236.22,956 1235.22,955 1158.22,1032 1153,1032 1153,1073.08 1154.92,1075 1157.92,1072 1166.67,1072
  pour cut-out: 1675.85,1497.94 1407,1229.09 1407,1026 1571.5,1026 1601,1055.5 1601,1167.12 1612.12,1167.12 1776,1331 1910,1331 1910,1627 1802,1735 1683.24,1735
  pour cut-out: 929.28,1450 929.28,1448.73 822.5,1341.95 827,1337.45 827,1269 924,1269 925,1268 927,1270 927,1449
  text ".Layer_Name" at 577,-858.49 h60
GND_PLANE (plane layer: these items are gaps in the copper):
  text ".Layer_Name" at 577,-858.49 h60
  text ".Layer_Name" at 577,-858.49 h60
POWER_PLANE (plane layer: these items are gaps in the copper):
  text ".Layer_Name" at 577,-858.49 h60
  text ".Layer_Name" at 577,-858.49 h60

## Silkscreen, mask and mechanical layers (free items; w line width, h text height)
Top Overlay:
  lines w10: 908.43,1688.28 965,1660 936.72,1716.57 908.43,1688.28
  text "GND" at 70,2975 h70
  text "EXT_CLOCK" at 50,2850 h60
  text "GND" at 1738.45,2810 h70
  text "STOP_EXT1" at 457,2715 h70 r90
  text "START _EXT1" at 1629,2650 h70 r90
  text "TRIG1" at 1340,2260 h60
  text "MSP_START" at 1630,2090 h60
  text "3.3V" at 35,2040 h70
  text "GND" at 1840,2020 h60
  text "DTG_TRIG" at 1075.83,2011 h60
  text "COMMON START" at 449,1832.7 h60
  text "ICC1" at 1485,1754.41 h70 r270
  text "CS1" at 1595,1555 h60
  text "ICC2" at 1480,1504.41 h70 r270
  text "SCLK" at 455,1285 h60
  text "CS2" at 1460,1230 h60
  text "TRIG2" at 1035,1155 h60
  text "DIN" at 1460,1125 h60
  text "DOUT2" at 459.1,1080 h60
  text "DOUT1" at 1345,950 h60
  text "TDC7201-ZAX-EVM" at 50,625 h100
  text "START _EXT2" at 409.82,450.41 h70 r270
  text "STOP_EXT2" at 1584.82,450.03 h70 r270
  text "GND" at 100,400 h70
  text "GND" at 1681,400 h70
  text ".Layer_Name" at 577,-858.49 h60
Bottom Overlay:
  rectangle: 891.91,725 1350,850
  text "_" at 1425,800 h100
  text ".PRJ_Number" at 1850,750 h100
  text "Rev. A" at 1825,650 h100
  text ".Layer_Name" at 577,-858.49 h60
Top Paste:
  text ".Layer_Name" at 577,-858.49 h60
Bottom Paste:
  text ".Layer_Name" at 577,-858.49 h60
Top Solder:
  text ".Layer_Name" at 577,-858.49 h60
  text ".Layer_Name" at 577,-858.49 h60
Bottom Solder:
  text ".Layer_Name" at 577,-858.49 h60
Drill Guide:
  text ".Layer_Name" at 577,-858.49 h60
M1 Board Outline:
  the board outline again, w10
  text ".Layer_Name" at 577,-858.49 h60
M2 Board Dimensions:
  rectangle: -0.5,-285.5 124.5,-160.5
  rectangle: 124.5,-410.5 499.5,-285.5
  lines w7: -0.5,-285.5 999.5,-285.5 ; 124.5,-410.5 124.5,-160.5 ; 249.5,-410.5 249.5,-160.5 ; 499.5,-410.5 499.5,-160.5 ; 749.5,-410.5 749.5,-160.5 ; -0.5,-410.5 999.5,-410.5 999.5,-160.5 -0.5,-160.5 -0.5,-410.5
  lines w10: -0.5,-475.5 -0.5,-455.5 ; 59.5,-485.5 -0.5,-465.5 ; 59.5,-445.5 -0.5,-465.5 ; 223.58,-465.5 -0.5,-465.5 ; 775.42,-465.5 999.5,-465.5 ; 939.5,-485.5 999.5,-465.5 ; 939.5,-445.5 999.5,-465.5 ; 999.5,-475.5 999.5,-455.5
  text "1000 (mil)" at 233.58,-501.49 h60
  text ".Layer_Name" at 577,-858.49 h60
M3 3D STEP Top:
  text ".Layer_Name" at 577,-858.49 h60
M4 3D STEP Bottom:
  text ".Layer_Name" at 577,-858.49 h60
M5 Assembly Top:
  lines w10: -292,-930.17 6308,-930.17 ; -292,-726.83 6310,-726.83 ; -292,-523.5 -292,-1133.5 3713,-1133.5 6310,-1133.5 6310,-523.5 -291.5,-523.5 -291.5,-1133.5 1284,-1133.5 ; 2173,-1133.5 2173,-523.5 ; 3440,-726.83 3440,-523.5 ; 4280,-726.83 4280,-523.5 ; 4902,-1140 4902,-937.17
  text "COMPONENTS MARKED 'DNP' SHOULD NOT BE POPULATED." at 1153.5,-318.5 h60
  text "ASSEMBLY VARIANT:" at 1153,-434 h60
  text ".VariantName" at 2189,-434 h60
  text "PCB VIEWED FROM TOP SIDE" at -228.5,-655.67 h60
  text "BOARD #:" at 2248,-655.67 h60
  text ".PRJ_Number" at 2793.5,-655.67 h60
  text "REV:" at 3638,-655.67 h60
  text ".PCB_Rev" at 3929.5,-655.67 h60
  text "SVN REV:" at 4476,-655.67 h60
  text ".VersionControl_RevNumber" at 4982,-655.67 h60
  text "TID #:" at 2248,-859 h60
  text ".TID" at 2793.5,-859 h60
  text "PLOT NAME =" at -228.5,-1064.34 h60
  text ".plot_File_Name" at 577,-1064.34 h60
  text "GENERATED    :" at 2250,-1064.34 h60
  text ".Print_Date" at 3119.5,-1064.34 h60
  text ".Print_Time" at 3848.5,-1064.34 h60
  text "TEXAS INSTRUMENTS" at 5113,-1064.34 h60
M6 Assembly Bottom:
  lines w10: -292.5,-727.33 6309.5,-727.33 ; -290.5,-930.67 6309.5,-930.67 ; 1115.5,-1140.5 1115.5,-937.67 ; 1737.5,-727.33 1737.5,-524 ; 2577.5,-727.33 2577.5,-524 ; 3844.5,-1134 3844.5,-524 ; 4733.5,-1134 6309,-1134 6309,-524 -292.5,-524 -292.5,-1134 2304.5,-1134 6309.5,-1134 6309.5,-524
  text "COMPONENTS MARKED 'DNP' SHOULD NOT BE POPULATED." at 6102,-318 h60
  text ".VariantName" at 5058,-434 h60
  text "ASSEMBLY VARIANT:" at 6097,-434 h60
  text ".VersionControl_RevNumber" at 1035.5,-656.17 h60
  text "SVN REV:" at 1541.5,-656.17 h60
  text ".PCB_Rev" at 2088,-656.17 h60
  text "REV:" at 2379.5,-656.17 h60
  text ".PRJ_Number" at 3224,-656.17 h60
  text "BOARD #:" at 3769.5,-656.17 h60
  text "PCB VIEWED FROM BOTTOM SIDE" at 6246,-656.17 h60
  text ".TID" at 3224,-859.5 h60
  text "TID #:" at 3769.5,-859.5 h60
  text "TEXAS INSTRUMENTS" at 904.5,-1064.84 h60
  text ".Print_Time" at 2169,-1064.84 h60
  text ".Print_Date" at 2898,-1064.84 h60
  text "GENERATED    :" at 3767.5,-1064.84 h60
  text ".plot_File_Name" at 5440.5,-1064.84 h60
  text "PLOT NAME =" at 6246,-1064.84 h60
M9 Title Sheet:
  drawing of 57 lines, arcs and shapes, not listed
  text "1" at 739.84,8036.5 h70
  text "2" at 3235.5,8036.5 h70
  text "3" at 5724.84,8036.5 h70
  text "4" at 8231.51,8036.5 h70
  text "5" at 10730.5,8036.5 h70
  text "6" at 13235.5,8036.5 h70
  text "A" at -416.5,6893.5 h70
  text "A" at 14383.5,6893.5 h70
  text "B" at -416.5,4513.5 h70
  text "B" at 14383.5,4513.5 h70
  text "C" at -416.5,2138.5 h70
  text "C" at 14383.5,2138.5 h70
  text "PROJECT TITLE:" at 11343.5,277.5 h45
  text ".PRJ_Title" at 11393.5,144.17 h70
  text "DESIGNED FOR:" at 11343.5,-23.5 h45
  text ".PRJ_Customer" at 11393.5,-163.5 h70
  text "D" at -416.5,-231.5 h70
  text "D" at 14383.5,-231.5 h70
  text "FILE NAME:" at 11343.5,-323.5 h45
  text ".PCB_File_Name_No_Path" at 11393.5,-443.5 h70
  text "Texas Instruments (TI) and/or its licensors do not warrant the accuracy or completeness of this specification" at 6374,-605.34 h45
  text "ENGINEER:" at 11343.5,-613.5 h45
  text "LAYOUT BY:" at 12848.5,-613.5 h45
  text "or any information contained therein. TI and/or its licensors do not warrant that this design will meet" at 6329.01,-718 h45
  text ".PRJ_Engineer" at 11393.5,-768.49 h70
  text ".PCB_Layout" at 12899,-768.49 h70
  text "the specifications, will be suitable for your application or fit for any particular purpose, or will operate in" at 6329.01,-830.67 h45
  text ".Layer_Name" at 577,-858.49 h60
  text "ALTIUM DESIGNER VERSION:" at 12848.5,-923.5 h45
  text "an implementation. TI and/or its licensors do not warrant that the design is production worthy. You should" at 6329.01,-943.33 h45
  text "completely validate and test your design implementation to confirm the system functionality for your application." at 6374,-1056 h45
  text ".print_Scale" at 11393.5,-1056.83 h70
  text ".Application_BuildNumber" at 12899,-1056.83 h70
  text "1" at 739.84,-1263.5 h70
  text "2" at 3235.5,-1263.5 h70
  text "3" at 5724.84,-1263.5 h70
  text "4" at 8231.51,-1263.5 h70
  text "5" at 10730.5,-1263.5 h70
  text "6" at 13235.5,-1263.5 h70
M10 Fab Notes:
  drawing of 217 lines, arcs and shapes, not listed
  text "DESIGN INFORMATION" at 12381.02,6810 h60
  text "(REFER ALSO ARRAY/PANEL PROFILING INFORMATION)" at 12019.46,6648.29 h60
  text "BOARD SIZE" at 11333.46,6644 h60
  text "3100MIL" at 11795.78,6516.18 h60
  text "X" at 12301.46,6516.18 h60
  text "2000MIL" at 12532.78,6516.18 h60
  text "Number of Layers :" at 11736.46,6319 h60
  text "4" at 12831.27,6309 h60
  text "MIN. TRACK WIDTH:" at 11736.46,6180 h60
  text "8" at 12832.7,6180 h60
  text "MIL" at 12987.46,6180 h60
  text "MIN. CLEARANCE:" at 11736.46,6048 h60
  text "5" at 12832.7,6048 h60
  text "MIL" at 12987.46,6048 h60
  text "MIN. VIA PAD SIZE:" at 11736.46,5916 h60
  text "12" at 12802.71,5916 h60
  text "MIL" at 12987.46,5916 h60
  text "0.05mm (2MIL)" at 12431.46,5774.29 h60
  text "MINIMUM ANNULAR RING" at 11407.23,5770 h60
  text "EXTERNAL" at 13139.46,5770 h60
  text "PER" at 11607.23,5652 h60
  text "IPC-D-275 CLASS 2 LEVEL C" at 11827.23,5652 h60
  text "MIL, HOLES" at 13315.46,5539.71 h60
  text "+/-" at 12923,5539 h60
  text "+/-" at 13777,5539 h60
  text "REGISTRATION TOLERANCES:" at 11407.23,5534 h60
  text "METAL" at 12607,5534 h60
  text "5" at 13183.2,5534 h60
  text "3" at 14016.2,5534 h60
  text "MIL" at 14132.46,5534 h60
  text "MATERIAL:" at 11332.46,5324.54 h60
  text "FR-4 High Tg" at 12318.9,5184.21 h60
  text "FR-408" at 11753.46,5175.64 h60
  text "X" at 12165.46,5175.64 h60
  text "OTHER" at 13241.46,5175.64 h60
  text "62 MIL (1.6mm) +/-10%" at 12073.56,5012.92 h60
  text "THICKNESS:" at 11407.23,5008.64 h60
  text "X" at 11945.4,5008.64 h60
  text "OTHER" at 13358.46,5008.64 h60
  text "TOLERANCE:" at 11407.23,4850.64 h60
  text "X" at 12246.53,4850.64 h60
  text "ANSI IPC-6012 TYPE 3 CLASS 2" at 12433.48,4850.64 h60
  text "OTHER +/-" at 12433.46,4694.64 h60
  text "BOW & TWIST:" at 11407.23,4537.64 h60
  text "X" at 12246.53,4537.64 h60
  text "ANSI IPC-6012 TYPE 3 CLASS 2" at 12433.48,4537.64 h60
  text "OTHER +/-" at 12433.46,4379.13 h60
  text "COPPER THICKNESS (FINISHED):" at 11332.46,4243.64 h60
  text "1.4MIL (1oz)" at 12212.46,4090.92 h60
  text "2MIL (1.4oz)" at 12979.46,4090.92 h60
  text "2.8MIL (2oz)" at 13706.46,4090.92 h60
  text "OUTER:" at 11689.46,4086.64 h60
  text "X" at 12084,4086 h60
  text "1.4MIL (1oz)" at 12212.46,3933.92 h60
  text "2.8MIL (2oz)" at 12979.46,3933.92 h60
  text "N/A" at 13706,3934.29 h60
  text "INNER SIGNAL:" at 11400.38,3929.64 h60
  text "X" at 12085.42,3929.64 h60
  text "DRILLING:" at 11332.46,3790.64 h60
  text "REFERENCE:" at 11407.23,3673.64 h60
  text "X" at 12055.46,3673.64 h60
  text "AS SHOWN" at 12242.46,3673.64 h60
  text "X" at 12956.46,3673.64 h60
  text "NC_DRILL FILES" at 13093.46,3673.64 h60
  text "PTH MIN COPPER THICKNESS:" at 11407.23,3515.64 h60
  text "X" at 12757.46,3515.64 h60
  text "1MIL" at 12894.46,3515.64 h60
  text "OTHER" at 13391.46,3515.64 h60
  text "BOARD FINISH:" at 11332.46,3356.64 h60
  text "SILKSCREEN:" at 11487.68,3238.64 h60
  text "X" at 12436.46,3238.64 h60
  text "TOP" at 12562.46,3238.64 h60
  text "X" at 12946.46,3238.64 h60
  text "BOTTOM" at 13073.46,3238.64 h60
  text "SILKSCREEN COLOR:" at 11487.68,3071.64 h60
  text "X" at 12435.42,3071.64 h60
  text "WHITE" at 12562.46,3071.64 h60
  text "OTHER" at 13073.46,3071.64 h60
  text "SOLDER RESIST COLOR:" at 11487.68,2901.64 h60
  text "RED" at 13720,2745 h60
  text "GREEN" at 12182.46,2742.44 h60
  text "BLUE" at 12773.46,2742.44 h60
  text "OTHER" at 13311.46,2742.44 h60
  text "X" at 13155,2735 h60
  text "IMMERSION GOLD (ENIG)" at 12393.46,2553.92 h60
  text "ENEPIG" at 13731,2550.64 h60
  text "SURFACE FINISH:" at 11332.46,2549.64 h60
  text "X" at 12206.51,2549.64 h60
  text "IMM. TIN/SILVER OR EQUIV" at 11662,2392.64 h60
  text "OTHER" at 13093.46,2392.64 h60
  text "X" at 12210,2225 h60
  text "ARRAY/PANEL:" at 11332.46,2213.64 h60
  text "CUT AND TRIM PER MECH LAYER 1" at 12393.46,2209.35 h60
  text "N.C. ROUTE" at 12393.46,2057.64 h60
  text "V. SCORE" at 13259.46,2057.64 h60
  text "CERTIFICATION:" at 11332.46,1920.64 h60
  text "MATERIALS AND WORKMANSHIP FOR ALL PCBS" at 12057.46,1920.64 h60
  text "TO MEET OR EXCEED THE REQUIREMENTS OF:" at 12057.46,1822.64 h60
  text "soldermask thickness must be maintained in this area." at 1350,1700 h40
  text "X" at 11683.96,1686.13 h60
  text "ANSI IPC-A-600F CLASS ->" at 11822.96,1686.13 h60
  text "X" at 13462.02,1686.13 h60
  text "2" at 13580.96,1686.14 h60
  text "1" at 13265.96,1684.64 h60
  text "3" at 13934.96,1684.64 h60
  text "X" at 11686.02,1526.64 h60
  text "UL 94V-0" at 11822.96,1526.64 h60
  text "X" at 12498.02,1526.64 h60
  text "RoHS" at 12634.96,1526.64 h60
  text "OTHER" at 13279.36,1526.64 h60
  text "PER ORDER" at 13676.42,1526.64 h60
  text "ADDITIONAL REQUIREMENTS:" at 11332.46,1385.64 h60
  text "MICROSECTION:" at 11407.23,1270.64 h60
  text "YES" at 12312.96,1270.64 h60
  text "REQUIRED" at 13174.46,1114.49 h60
  text "BARE BOARD ELEC. TEST:" at 11407.23,1111.64 h60
  text "NONE" at 12712.96,1111.64 h60
  text "X" at 13047.46,1111.64 h60
  text "PER ORDER" at 13766.46,1111.64 h60
  text "MANUFACTURER'S UL:" at 11407.23,954.64 h60
  text "RAIL" at 12572.96,950.35 h60
  text "METAL" at 13064.77,950.35 h60
  text "X" at 13440,950 h60
  text "SILK" at 13576.46,950.35 h60
  text ".Layer_Name" at 577,-858.49 h60
M11 Gerber Information:
  lines w10: -292,-930.17 6308,-930.17 ; -292,-726.83 6310,-726.83 ; -292,-523.5 -292,-1133.5 3713,-1133.5 6310,-1133.5 6310,-523.5 -291.5,-523.5 -291.5,-1133.5 1284,-1133.5 ; 2173,-1133.5 2173,-523.5 ; 3440,-726.83 3440,-523.5 ; 4280,-726.83 4280,-523.5 ; 4902,-1140 4902,-937.17
  text "ALL ARTWORK VIEWED FROM TOP SIDE" at -228.5,-655.67 h60
  text "BOARD #:" at 2248,-655.67 h60
  text ".PRJ_Number" at 2793.5,-655.67 h60
  text "REV:" at 3638,-655.67 h60
  text ".PCB_Rev" at 3929.5,-655.67 h60
  text "SVN REV:" at 4476,-655.67 h60
  text ".VersionControl_RevNumber" at 4982,-655.67 h60
  text "LAYER NAME =" at -228.5,-858.49 h60
  text "PLOT NAME =" at -228.5,-1064.34 h60
  text ".plot_File_Name" at 577,-1064.34 h60
  text "GENERATED    :" at 2250,-1064.34 h60
  text ".Print_Date" at 3119.5,-1064.34 h60
  text ".Print_Time" at 3848.5,-1064.34 h60
  text "TEXAS INSTRUMENTS" at 5113,-1064.34 h60
M12 Stackup:
  drawing of 295 lines, arcs and shapes, not listed
  text "Layer" at 6256.2,7655 h60
  text "Name" at 6666.11,7655 h60
  text "Material" at 7595.85,7655 h60
  text "Thickness" at 8455.62,7655 h60
  text "Constant" at 9105.46,7655 h60
  text "Board Layer Stack" at 9675.32,7655 h60
  text "1" at 6256.2,7535 h60
  text "Top Overlay" at 6666.11,7535 h60
  text "2" at 6256.2,7415 h60
  text "Top Solder" at 6666.11,7415 h60
  text "Solder Resist" at 7595.85,7415 h60
  text "0.40mil" at 8455.62,7415 h60
  text "3.5" at 9105.46,7415 h60
  text "3" at 6256.2,7295 h60
  text "Top Layer" at 6666.11,7295 h60
  text "Copper" at 7595.85,7295 h60
  text "1.40mil" at 8455.62,7295 h60
  text "4" at 6256.2,7175 h60
  text "Dielectric1" at 6666.11,7175 h60
  text "FR-4 High TG" at 7595.85,7175 h60
  text "12.60mil" at 8455.62,7175 h60
  text "4.8" at 9105.46,7175 h60
  text "5" at 6256.2,7055 h60
  text "GND_PLANE" at 6666.11,7055 h60
  text "Copper" at 7595.85,7055 h60
  text "1.40mil" at 8455.62,7055 h60
  text "6" at 6256.2,6935 h60
  text "Dielectric2" at 6666.11,6935 h60
  text "FR-4 High TG" at 7595.85,6935 h60
  text "30.00mil" at 8455.62,6935 h60
  text "4.8" at 9105.46,6935 h60
  text "7" at 6256.2,6815 h60
  text "POWER_PLANE" at 6666.11,6815 h60
  text "Copper" at 7595.85,6815 h60
  text "1.40mil" at 8455.62,6815 h60
  text "8" at 6256.2,6695 h60
  text "Dielectric3" at 6666.11,6695 h60
  text "FR-4 High TG" at 7595.85,6695 h60
  text "12.60mil" at 8455.62,6695 h60
  text "4.8" at 9105.46,6695 h60
  text "9" at 6256.2,6575 h60
  text "Bottom Layer" at 6666.11,6575 h60
  text "Copper" at 7595.85,6575 h60
  text "1.40mil" at 8455.62,6575 h60
  text "10" at 6256.2,6455 h60
  text "Bottom Solder" at 6666.11,6455 h60
  text "Solder Resist" at 7595.85,6455 h60
  text "0.40mil" at 8455.62,6455 h60
  text "3.5" at 9105.46,6455 h60
  text "11" at 6256.2,6335 h60
  text "Bottom Overlay" at 6666.11,6335 h60
  text ".Layer_Name" at 577,-858.49 h60
M13 Component Bodies Top:
  text ".Layer_Name" at 577,-858.49 h60
M14 Component Bodies Bottom:
  text ".Layer_Name" at 577,-858.49 h60
M15 Courtyards Top:
  text ".Layer_Name" at 577,-858.49 h60
M16 Courtyards Bottom:
  text ".Layer_Name" at 577,-858.49 h60
Drill Drawing:
  circle w10: c6300.62,5585.83 r20
  circle w10: c6300.62,5585.83 r33.33
  lines w1: 2000,3100 2000.03,3100 ; 0,0 0.03,0 ; 0,0 0.03,0 ; 0,0 0.03,0 ; 0,3100 0.03,3100 0,3100 ; 100,1050 100.03,1050 100,1050
  lines w10: 6267.29,4719.17 6333.96,4719.17 6300.62,4652.5 6267.29,4719.17 ; 6267.29,4952.5 6267.29,4969.17 6283.96,4985.83 6267.29,5002.5 6267.29,5019.17 6283.96,5019.17 6300.62,5002.5 6317.29,5019.17 6333.96,5019.17 6333.96,5002.5 6317.29,4985.83 6333.96,4969.17 6333.96,4952.5 6317.29,4952.5 6300.62,4969.17 6283.96,4952.5 6267.29,4952.5 ; 6267.29,5119.17 6283.96,5119.17 6300.62,5102.5 6317.29,5119.17 6333.96,5119.17 6317.29,5135.83 6333.96,5152.5 6317.29,5152.5 6300.62,5169.17 6283.96,5152.5 6267.29,5152.5 6283.96,5135.83 6267.29,5119.17 ; 6267.29,5269.17 6283.96,5269.17 6283.96,5252.5 6317.29,5252.5 6317.29,5269.17 6333.96,5269.17 6333.96,5302.5 6317.29,5302.5 6317.29,5319.17 6283.96,5319.17 6283.96,5302.5 6267.29,5302.5 6267.29,5269.17 ; 6267.29,5402.5 6333.96,5402.5 6333.96,5469.17 6267.29,5469.17 6267.29,5402.5 ; 6267.29,5702.5 6300.62,5719.17 6333.96,5702.5 6317.29,5735.83 6333.96,5769.17 6300.62,5752.5 6267.29,5769.17 6283.96,5735.83 6267.29,5702.5 ; 6280.62,4705.83 6320.62,4705.83 6300.62,4665.83 6280.62,4705.83 ; 6280.62,4965.83 6280.62,4975.83 6290.62,4985.83 6280.62,4995.83 6280.62,5005.83 6290.62,5005.83 6300.62,4995.83 6310.62,5005.83 6320.62,5005.83 6320.62,4995.83 6310.62,4985.83 6320.62,4975.83 6320.62,4965.83 6310.62,4965.83 6300.62,4975.83 6290.62,4965.83 6280.62,4965.83 ; 6280.62,5125.83 6290.62,5125.83 6300.62,5115.83 6310.62,5125.83 6320.62,5125.83 6310.62,5135.83 6320.62,5145.83 6310.62,5145.83 6300.62,5155.83 6290.62,5145.83 6280.62,5145.83 6290.62,5135.83 6280.62,5125.83 ; 6280.62,5275.83 6290.62,5275.83 6290.62,5265.83 6310.62,5265.83 6310.62,5275.83 6320.62,5275.83 6320.62,5295.83 6310.62,5295.83 6310.62,5305.83 6290.62,5305.83 6290.62,5295.83 6280.62,5295.83 6280.62,5275.83 ; 6280.62,5415.83 6320.62,5415.83 6320.62,5455.83 6280.62,5455.83 6280.62,5415.83 ; 6280.62,5715.83 6300.62,5725.83 6320.62,5715.83 6310.62,5735.83 6320.62,5755.83 6300.62,5745.83 6280.62,5755.83 6290.62,5735.83 6280.62,5715.83
  lines w15: 6207.5,4607.5 10086.47,4607.5 ; 6207.5,5807.5 10086.47,5807.5 ; 6758.38,4457.5 6758.38,5957.5 ; 7456.19,4457.5 7456.19,5957.5 ; 8801.79,4457.5 8801.79,5957.5 ; 9307.67,4457.5 9307.67,5957.5 ; 6207.5,4457.5 10086.47,4457.5 10086.47,5957.5 6207.5,5957.5 6207.5,4457.5
  text "Symbol" at 6297.5,5852.5 h72
  text "Hit Count" at 6803.38,5852.5 h72
  text "Finished Hole Size" at 7501.19,5852.5 h72
  text "Plated" at 8846.79,5852.5 h72
  text "Hole Type" at 9352.67,5852.5 h72
  text "2" at 6803.38,5702.5 h60
  text "62.00mil (1.575mm)" at 7501.19,5702.5 h60
  text "PTH" at 8846.79,5702.5 h60
  text "Round" at 9352.67,5702.5 h60
  text "4" at 6803.38,5552.5 h60
  text "63.00mil (1.600mm)" at 7501.19,5552.5 h60
  text "PTH" at 8846.79,5552.5 h60
  text "Round" at 9352.67,5552.5 h60
  text "6" at 6803.38,5402.5 h60
  text "35.00mil (0.889mm)" at 7501.19,5402.5 h60
  text "PTH" at 8846.79,5402.5 h60
  text "Round" at 9352.67,5402.5 h60
  text "8" at 6803.38,5252.5 h60
  text "67.00mil (1.702mm)" at 7501.19,5252.5 h60
  text "PTH" at 8846.79,5252.5 h60
  text "Round" at 9352.67,5252.5 h60
  text "10" at 6803.38,5102.5 h60
  text "18.00mil (0.457mm)" at 7501.19,5102.5 h60
  text "PTH" at 8846.79,5102.5 h60
  text "Round" at 9352.67,5102.5 h60
  text "19" at 6803.38,4952.5 h60
  text "6.00mil (0.152mm)" at 7501.19,4952.5 h60
  text "PTH" at 8846.79,4952.5 h60
  text "Round" at 9352.67,4952.5 h60
  text "36" at 6803.38,4802.5 h60
  text "10.00mil (0.254mm)" at 7501.19,4802.5 h60
  text "PTH" at 8846.79,4802.5 h60
  text "Round" at 9352.67,4802.5 h60
  text "A" at 6268.41,4792.51 h66.67
  text "51" at 6803.38,4652.5 h60
  text "40.00mil (1.016mm)" at 7501.19,4652.5 h60
  text "PTH" at 8846.79,4652.5 h60
  text "Round" at 9352.67,4652.5 h60
  text "136 Total" at 6803.38,4502.5 h60
  text ".Layer_Name" at 577,-858.49 h60

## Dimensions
0,0 to 0,3100 on M2 Board Dimensions
0,0 to 2000,0 on M2 Board Dimensions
